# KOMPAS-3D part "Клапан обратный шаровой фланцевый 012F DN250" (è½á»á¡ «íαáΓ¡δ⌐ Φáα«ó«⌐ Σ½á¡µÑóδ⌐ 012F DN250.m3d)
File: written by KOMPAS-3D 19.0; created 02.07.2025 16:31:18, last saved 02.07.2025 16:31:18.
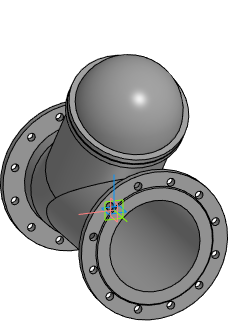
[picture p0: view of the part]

Document properties: Полное имя файла: E:\Dendor Работа Сачек\3D для проектировщиков\5.3 Тип 012F, 012F.Z Клапан обратный шаровой фланцевый\stp_Клапан обратный шаровой фланцевый 012F\Клапан обратный шаровой фланцевый 012F DN250.m3d

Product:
- Part/product: Клапан обратный шаровой фланцевый 012F DN250

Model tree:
1. Операция без истории:1  (labels: Клапан обратный шаровой фланцевый 012F DN250)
